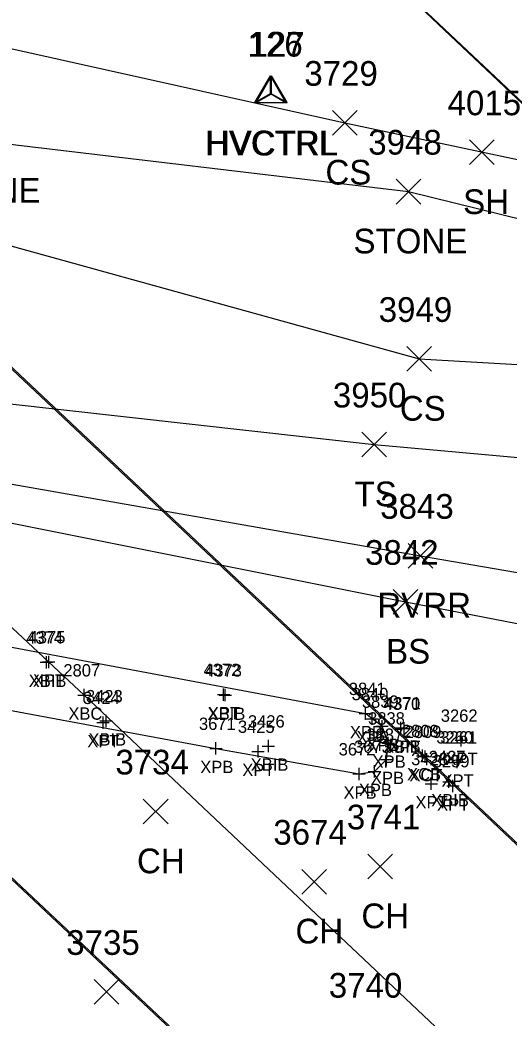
# Model space of a CAD drawing. Extents: x 1647574 to 1652703, y 212895 to 228670.
# Drawn here: x 1648798.3 to 1648837.9, y 227257.1 to 227337.9 of the extents above; entities that cross this region are included whole.
import ezdxf

# ---------------------------------------------------------------- set-up
doc = ezdxf.new("R2010")
doc.units = 0
for name, color, linetype in [('B_A', 7, 'Continuous'), ('B_I', 7, 'Continuous'), ('B_TIC', 7, 'Continuous'), ('BDC', 7, 'Continuous'), ('BELB', 7, 'Continuous'), ('BSUBM', 7, 'Continuous'), ('C_A', 7, 'Continuous'), ('C_I', 7, 'Continuous'), ('CPSM', 7, 'Continuous'), ('L_A', 7, 'Continuous'), ('L_I', 7, 'Continuous'), ('L_TIC', 7, 'Continuous'), ('LASF', 7, 'Continuous'), ('LAWE', 7, 'Continuous'), ('LELB', 7, 'Continuous')]:
    doc.layers.add(name, color=color, linetype=linetype)

msp = doc.modelspace()

# ---------------------------------------------------------------- linework, layer by layer
at = {"layer": 'B_TIC'}
for p, q in [((1648800.414, 227285.861), (1648800.49, 227285.861)), ((1648800.609, 227285.9), (1648800.684, 227285.9)), ((1648803.46, 227283.214), (1648803.535, 227283.214)), ((1648814.759, 227283.253), (1648814.835, 227283.253)), ((1648814.893, 227283.203), (1648814.969, 227283.203)), ((1648805.249, 227281.12), (1648805.324, 227281.12)), ((1648826.241, 227281.71), (1648826.317, 227281.71)), ((1648826.241, 227281.71), (1648826.317, 227281.71)), ((1648826.796, 227281.294), (1648826.871, 227281.294)), ((1648805.005, 227280.984), (1648805.081, 227280.984)), ((1648827.584, 227280.681), (1648827.659, 227280.681)), ((1648829.094, 227280.543), (1648829.17, 227280.543)), ((1648829.372, 227280.51), (1648829.448, 227280.51)), ((1648833.992, 227279.546), (1648834.068, 227279.546)), ((1648814.134, 227278.885), (1648814.21, 227278.885)), ((1648817.547, 227278.644), (1648817.622, 227278.644)), ((1648818.383, 227279.076), (1648818.458, 227279.076)), ((1648828.083, 227279.32), (1648828.159, 227279.32)), ((1648827.952, 227278.001), (1648828.028, 227278.001)), ((1648830.866, 227278.3), (1648830.942, 227278.3)), ((1648831.081, 227278.232), (1648831.157, 227278.232)), ((1648833.673, 227277.785), (1648833.749, 227277.785)), ((1648833.675, 227277.784), (1648833.75, 227277.784)), ((1648826.971, 227277.031), (1648827.046, 227277.031)), ((1648825.725, 227276.819), (1648825.8, 227276.819)), ((1648832.989, 227276.194), (1648833.065, 227276.194)), ((1648831.566, 227276.03), (1648831.642, 227276.03)), ((1648833.315, 227275.857), (1648833.391, 227275.857))]:
    msp.add_line(p, q, dxfattribs=at)
for points in [[(1648799.911, 227285.861), (1648800.911, 227285.861)], [(1648800.105, 227285.9), (1648801.105, 227285.9)], [(1648800.411, 227285.361), (1648800.411, 227286.361)], [(1648800.605, 227285.4), (1648800.605, 227286.4)], [(1648803.456, 227282.714), (1648803.456, 227283.714)], [(1648814.756, 227282.753), (1648814.756, 227283.753)], [(1648814.89, 227282.703), (1648814.89, 227283.703)], [(1648802.956, 227283.214), (1648803.956, 227283.214)], [(1648814.256, 227283.253), (1648815.256, 227283.253)], [(1648814.39, 227283.203), (1648815.39, 227283.203)], [(1648826.238, 227281.21), (1648826.238, 227282.21)], [(1648826.238, 227281.21), (1648826.238, 227282.21)], [(1648804.745, 227281.12), (1648805.745, 227281.12)], [(1648805.002, 227280.484), (1648805.002, 227281.484)], [(1648805.245, 227280.62), (1648805.245, 227281.62)], [(1648825.738, 227281.71), (1648826.738, 227281.71)], [(1648825.738, 227281.71), (1648826.738, 227281.71)], [(1648826.292, 227281.294), (1648827.292, 227281.294)], [(1648826.792, 227280.794), (1648826.792, 227281.794)], [(1648827.58, 227280.181), (1648827.58, 227281.181)], [(1648829.091, 227280.043), (1648829.091, 227281.043)], [(1648829.369, 227280.01), (1648829.369, 227281.01)], [(1648804.502, 227280.984), (1648805.502, 227280.984)], [(1648827.08, 227280.681), (1648828.08, 227280.681)], [(1648828.591, 227280.543), (1648829.591, 227280.543)], [(1648828.869, 227280.51), (1648829.869, 227280.51)], [(1648814.131, 227278.385), (1648814.131, 227279.385)], [(1648818.379, 227278.576), (1648818.379, 227279.576)], [(1648828.08, 227278.82), (1648828.08, 227279.82)], [(1648833.489, 227279.546), (1648834.489, 227279.546)], [(1648833.989, 227279.046), (1648833.989, 227280.046)], [(1648813.631, 227278.885), (1648814.631, 227278.885)], [(1648817.043, 227278.644), (1648818.043, 227278.644)], [(1648817.543, 227278.144), (1648817.543, 227279.144)], [(1648817.879, 227279.076), (1648818.879, 227279.076)], [(1648827.58, 227279.32), (1648828.58, 227279.32)], [(1648830.863, 227277.8), (1648830.863, 227278.8)], [(1648831.078, 227277.732), (1648831.078, 227278.732)], [(1648827.449, 227278.001), (1648828.449, 227278.001)], [(1648827.949, 227277.501), (1648827.949, 227278.501)], [(1648830.363, 227278.3), (1648831.363, 227278.3)], [(1648830.578, 227278.232), (1648831.578, 227278.232)], [(1648833.17, 227277.785), (1648834.17, 227277.785)], [(1648833.171, 227277.784), (1648834.171, 227277.784)], [(1648833.67, 227277.285), (1648833.67, 227278.285)], [(1648833.671, 227277.284), (1648833.671, 227278.284)], [(1648825.721, 227276.319), (1648825.721, 227277.319)], [(1648826.467, 227277.031), (1648827.467, 227277.031)], [(1648826.967, 227276.531), (1648826.967, 227277.531)], [(1648825.221, 227276.819), (1648826.221, 227276.819)], [(1648831.563, 227275.53), (1648831.563, 227276.53)], [(1648832.486, 227276.194), (1648833.486, 227276.194)], [(1648832.986, 227275.694), (1648832.986, 227276.694)], [(1648833.312, 227275.357), (1648833.312, 227276.357)], [(1648831.063, 227276.03), (1648832.063, 227276.03)], [(1648832.812, 227275.857), (1648833.812, 227275.857)]]:
    msp.add_lwpolyline(points, dxfattribs=at)
at = {"layer": 'BDC'}
for points in [[(1648650.624, 227406.773), (1648690.525, 227369.254), (1648733.472, 227328.732), (1648776.312, 227288.32), (1648833.664, 227234.301), (1648891.231, 227180.054), (1648955.856, 227118.961), (1649002.635, 227075.018), (1649045.277, 227034.596)], [(1648651.076, 227406.804), (1648690.742, 227369.256), (1648733.458, 227328.853), (1648776.322, 227288.427), (1648833.713, 227234.413), (1648891.304, 227180.165), (1648955.952, 227119.198), (1649002.814, 227075.033), (1649045.282, 227034.879)], [(1648705.852, 227396.154), (1648745.059, 227359.411), (1648787.916, 227318.711), (1648830.863, 227278.3), (1648888.33, 227224.067), (1648945.958, 227169.85), (1649010.577, 227108.866), (1649057.241, 227064.803), (1649099.962, 227024.603)], [(1648705.902, 227396.256), (1648745.142, 227359.215), (1648788.072, 227318.717), (1648831.078, 227278.232), (1648888.572, 227223.976), (1648945.897, 227169.932), (1649010.764, 227109.119), (1649057.374, 227064.845), (1649100.019, 227024.673)], [(1649190.777, 226999.084), (1649140.468, 227046.558), (1649090.33, 227093.733), (1649025.71, 227154.751), (1648968.186, 227208.898), (1648910.789, 227263.155), (1648860.431, 227310.794), (1648808.664, 227359.741)], [(1649190.944, 226999.114), (1649140.59, 227046.719), (1649090.397, 227093.864), (1649025.741, 227154.791), (1648968.355, 227208.988), (1648910.836, 227263.351), (1648860.59, 227310.809), (1648808.767, 227359.651)]]:
    msp.add_lwpolyline(points, dxfattribs=at)
at = {"layer": 'BELB'}
msp.add_lwpolyline([(1648676.128, 227401.909), (1648716.738, 227364.514), (1648759.552, 227324.27), (1648803.456, 227283.214), (1648860.317, 227229.513), (1648917.836, 227175.012), (1648982.231, 227114.435), (1649029.643, 227069.952), (1649071.001, 227030.272)], dxfattribs=at)
at = {"layer": 'BSUBM'}
for points in [[(1648782.195, 227289.97), (1648780.325, 227289.713), (1648779.199, 227287.978), (1648779.501, 227286.472), (1648781.154, 227285.028), (1648795.503, 227282.328), (1648814.131, 227278.885), (1648825.721, 227276.819), (1648826.967, 227277.031), (1648827.949, 227278.001), (1648828.08, 227279.32), (1648827.58, 227280.681), (1648826.792, 227281.294), (1648826.238, 227281.71)], [(1648782.195, 227289.97), (1648826.238, 227281.71)]]:
    msp.add_lwpolyline(points, dxfattribs=at)
at = {"layer": 'CPSM'}
for p, q in [((1648817.294, 227331.198), (1648818.544, 227333.363)), ((1648817.388, 227331.188), (1648818.638, 227333.353)), ((1648819.794, 227331.198), (1648818.544, 227333.363)), ((1648818.545, 227331.919), (1648818.544, 227333.363)), ((1648819.888, 227331.188), (1648818.638, 227333.353)), ((1648818.639, 227331.909), (1648818.638, 227333.353)), ((1648817.294, 227331.198), (1648818.545, 227331.919)), ((1648818.545, 227331.919), (1648818.545, 227331.919)), ((1648818.545, 227331.919), (1648819.794, 227331.198)), ((1648817.294, 227331.198), (1648819.794, 227331.198)), ((1648817.388, 227331.188), (1648818.639, 227331.909)), ((1648817.388, 227331.188), (1648819.888, 227331.188)), ((1648818.639, 227331.909), (1648818.639, 227331.909)), ((1648818.639, 227331.909), (1648819.888, 227331.188))]:
    msp.add_line(p, q, dxfattribs=at)
at = {"layer": 'L_TIC'}
for points in [[(1648823.556, 227328.555), (1648825.556, 227330.555)], [(1648825.556, 227328.555), (1648823.556, 227330.555)], [(1648834.654, 227326.168), (1648836.654, 227328.168)], [(1648836.654, 227326.168), (1648834.654, 227328.168)], [(1648828.721, 227322.979), (1648830.721, 227324.979)], [(1648830.721, 227322.979), (1648828.721, 227324.979)], [(1648829.575, 227309.433), (1648831.575, 227311.433)], [(1648831.575, 227309.433), (1648829.575, 227311.433)], [(1648825.946, 227302.501), (1648827.946, 227304.501)], [(1648827.946, 227302.501), (1648825.946, 227304.501)], [(1648829.69, 227293.491), (1648831.69, 227295.491)], [(1648831.69, 227293.491), (1648829.69, 227295.491)], [(1648828.465, 227289.758), (1648830.465, 227291.758)], [(1648830.465, 227289.758), (1648828.465, 227291.758)], [(1648808.256, 227272.778), (1648810.256, 227274.778)], [(1648810.256, 227272.778), (1648808.256, 227274.778)], [(1648826.421, 227268.331), (1648828.421, 227270.331)], [(1648828.421, 227268.331), (1648826.421, 227270.331)], [(1648821.084, 227267.093), (1648823.084, 227269.093)], [(1648823.084, 227267.093), (1648821.084, 227269.093)], [(1648804.28, 227258.17), (1648806.28, 227260.17)], [(1648806.28, 227258.17), (1648804.28, 227260.17)]]:
    msp.add_lwpolyline(points, dxfattribs=at)
at = {"layer": 'LASF'}
msp.add_lwpolyline([(1648650.222, 227380.955), (1648665.187, 227366.232), (1648704.752, 227348.923), (1648726.242, 227345.003), (1648748.022, 227340.215), (1648778.691, 227335.468), (1648795.179, 227328.09), (1648829.721, 227323.979), (1648869.231, 227314.255), (1648889.736, 227315.356), (1648906.07, 227312.609), (1648918.662, 227314.372), (1648951.491, 227306.349), (1648977.567, 227292.251), (1648987.29, 227278.611), (1648987.249, 227274.742)], dxfattribs=at)
at = {"layer": 'LAWE'}
msp.add_lwpolyline([(1648523.618, 227464.437), (1648558.315, 227431.33), (1648577.139, 227410.096), (1648589.542, 227390.215), (1648614.463, 227367.163), (1648643.493, 227349.685), (1648671.906, 227332.593), (1648697.558, 227323.897), (1648718.58, 227316.224), (1648748.456, 227309.789), (1648786.397, 227302.267), (1648830.69, 227294.491), (1648864.898, 227288.599), (1648895.304, 227284.453), (1648918.106, 227285.909), (1648972.006, 227267.699), (1649004.518, 227260.095), (1649036.332, 227254.751), (1649067.753, 227244.931), (1649099.556, 227239.623), (1649133.345, 227233.557), (1649168.721, 227227.534), (1649200.785, 227221.115), (1649219.753, 227218.741)], dxfattribs=at)
at = {"layer": 'LELB'}
for points in [[(1648655.911, 227395.863), (1648674.999, 227378.757), (1648703.409, 227359.468), (1648723.983, 227350.839), (1648755.179, 227345.024), (1648824.556, 227329.555), (1648858.755, 227322.284), (1648879.14, 227320.58)], [(1648624.782, 227367.39), (1648661.563, 227343.255), (1648687.991, 227330.789), (1648710.881, 227324.59), (1648732.4, 227320.11), (1648758.291, 227314.941), (1648781.981, 227308.526), (1648826.946, 227303.501), (1648863.734, 227300.174), (1648907.545, 227292.016), (1648945.167, 227284.729), (1648987.249, 227274.742), (1649006.387, 227273.993), (1649032.821, 227270.544), (1649043.18, 227273.015), (1649036.389, 227297.452)], [(1648717.8, 227336.794), (1648782.39, 227323.788), (1648830.575, 227310.433), (1648862.859, 227308.566)], [(1648785.473, 227299.553), (1648829.465, 227290.758), (1648865.217, 227283.832), (1648894.895, 227281.32), (1648915.213, 227276.631), (1648970.743, 227264.412), (1649004.316, 227256.615), (1649035.751, 227252.607), (1649067.455, 227243.568), (1649099.248, 227238.183), (1649133.364, 227231.231), (1649168.074, 227224.491), (1649200.359, 227218.768), (1649219.225, 227216.606)]]:
    msp.add_lwpolyline(points, dxfattribs=at)

# ---------------------------------------------------------------- texts
at = {"layer": 'B_A'}
for s, p in [('XBIB', (1648798.982, 227283.861)), ('XPT', (1648799.326, 227283.9)), ('XBC', (1648802.192, 227281.214)), ('XBIB', (1648813.461, 227281.203)), ('XPT', (1648813.476, 227281.253)), ('XPB', (1648824.974, 227279.71)), ('XPB', (1648824.974, 227279.71)), ('XPB', (1648825.529, 227279.294)), ('XPT', (1648803.722, 227278.984)), ('XBIB', (1648803.816, 227279.12)), ('XPB', (1648826.317, 227278.681)), ('XBIB', (1648827.662, 227278.543)), ('XPT', (1648828.089, 227278.51)), ('XPB', (1648812.867, 227276.885)), ('XBIB', (1648816.95, 227277.076)), ('XPB', (1648826.816, 227277.32)), ('XPT', (1648832.709, 227277.546)), ('XPT', (1648816.264, 227276.644)), ('XPB', (1648826.685, 227276.001)), ('XCB', (1648829.599, 227276.3)), ('XCT', (1648829.798, 227276.232)), ('XPT', (1648832.39, 227275.785)), ('XPT', (1648832.392, 227275.784)), ('XPB', (1648824.458, 227274.819)), ('XPB', (1648825.704, 227275.031)), ('XPT', (1648830.283, 227274.03)), ('XBIB', (1648831.557, 227274.194)), ('XPT', (1648832.032, 227273.857))]:
    msp.add_text(s, height=1, dxfattribs=at).set_placement(p)
at = {"layer": 'B_I'}
for s, p in [('4374', (1648798.781, 227287.361)), ('4375', (1648798.976, 227287.4)), ('2807', (1648801.787, 227284.714)), ('4372', (1648813.126, 227284.753)), ('4373', (1648813.26, 227284.703)), ('3841', (1648824.891, 227283.21)), ('3841', (1648824.891, 227283.21)), ('3424', (1648803.372, 227282.484)), ('3423', (1648803.615, 227282.62)), ('3840', (1648825.119, 227282.794)), ('3839', (1648825.947, 227282.181)), ('4370', (1648827.695, 227282.01)), ('4371', (1648827.744, 227282.043)), ('3838', (1648826.45, 227280.82)), ('3262', (1648832.335, 227281.046)), ('3671', (1648812.761, 227280.385)), ('3425', (1648815.913, 227280.144)), ('3426', (1648816.722, 227280.576)), ('3837', (1648826.319, 227279.501)), ('2808', (1648829.193, 227279.8)), ('2809', (1648829.405, 227279.732)), ('3260', (1648831.973, 227279.285)), ('3261', (1648832.301, 227279.284)), ('3673', (1648825.314, 227278.531)), ('3672', (1648824.068, 227278.319)), ('3427', (1648831.356, 227277.694)), ('3428', (1648829.933, 227277.53)), ('3259', (1648831.678, 227277.357))]:
    msp.add_text(s, height=1, dxfattribs=at).set_placement(p)
at = {"layer": 'C_A'}
for p in [(1648813.238, 227326.919), (1648813.332, 227326.909)]:
    msp.add_text('HVCTRL', height=2, dxfattribs=at).set_placement(p)
at = {"layer": 'C_I'}
for s, p in [('126', (1648816.695, 227334.919)), ('127', (1648816.844, 227334.909))]:
    msp.add_text(s, height=2, dxfattribs=at).set_placement(p)
at = {"layer": 'L_A'}
for s, p in [('CS', (1648822.997, 227324.555)), ('STONE', (1648790.722, 227323.09)), ('SH', (1648834.142, 227322.168)), ('STONE', (1648825.265, 227318.979)), ('CS', (1648829.016, 227305.433)), ('TS', (1648825.356, 227298.501)), ('RVRR', (1648827.201, 227289.491)), ('BS', (1648827.906, 227285.758)), ('CH', (1648807.744, 227268.778)), ('CH', (1648825.909, 227264.331)), ('CH', (1648820.572, 227263.093))]:
    msp.add_text(s, height=2, dxfattribs=at).set_placement(p)
at = {"layer": 'L_I'}
for s, p in [('3729', (1648821.288, 227332.555)), ('4015', (1648832.883, 227330.168)), ('3948', (1648826.462, 227326.979)), ('3949', (1648827.307, 227313.433)), ('3950', (1648823.6, 227306.501)), ('3843', (1648827.43, 227297.491)), ('3842', (1648826.206, 227293.758)), ('3734', (1648805.996, 227276.778)), ('3741', (1648824.728, 227272.331)), ('3674', (1648818.777, 227271.093)), ('3735', (1648802.02, 227262.17)), ('3740', (1648823.269, 227258.702))]:
    msp.add_text(s, height=2, dxfattribs=at).set_placement(p)

doc.saveas('drawing.dxf')
